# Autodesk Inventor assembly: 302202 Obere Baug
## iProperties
Created: 2006-12
Part Number: 302202 Obere Baug
Cost Center: 0 kg
Document SubType Name: Assembly
Designer: Martin
Authority: 0 mm^3
Mass: 52455 g
Surface Area: 13682 cm^2
Volume: 7141.43 cm^3
Density: 7.34516 g/cm^3
SaveDate: 2004-08-02
SaveTime: 16:43
TotalMass: 0 kg
TotalVolume: 0 mm^3
Author: Martin
